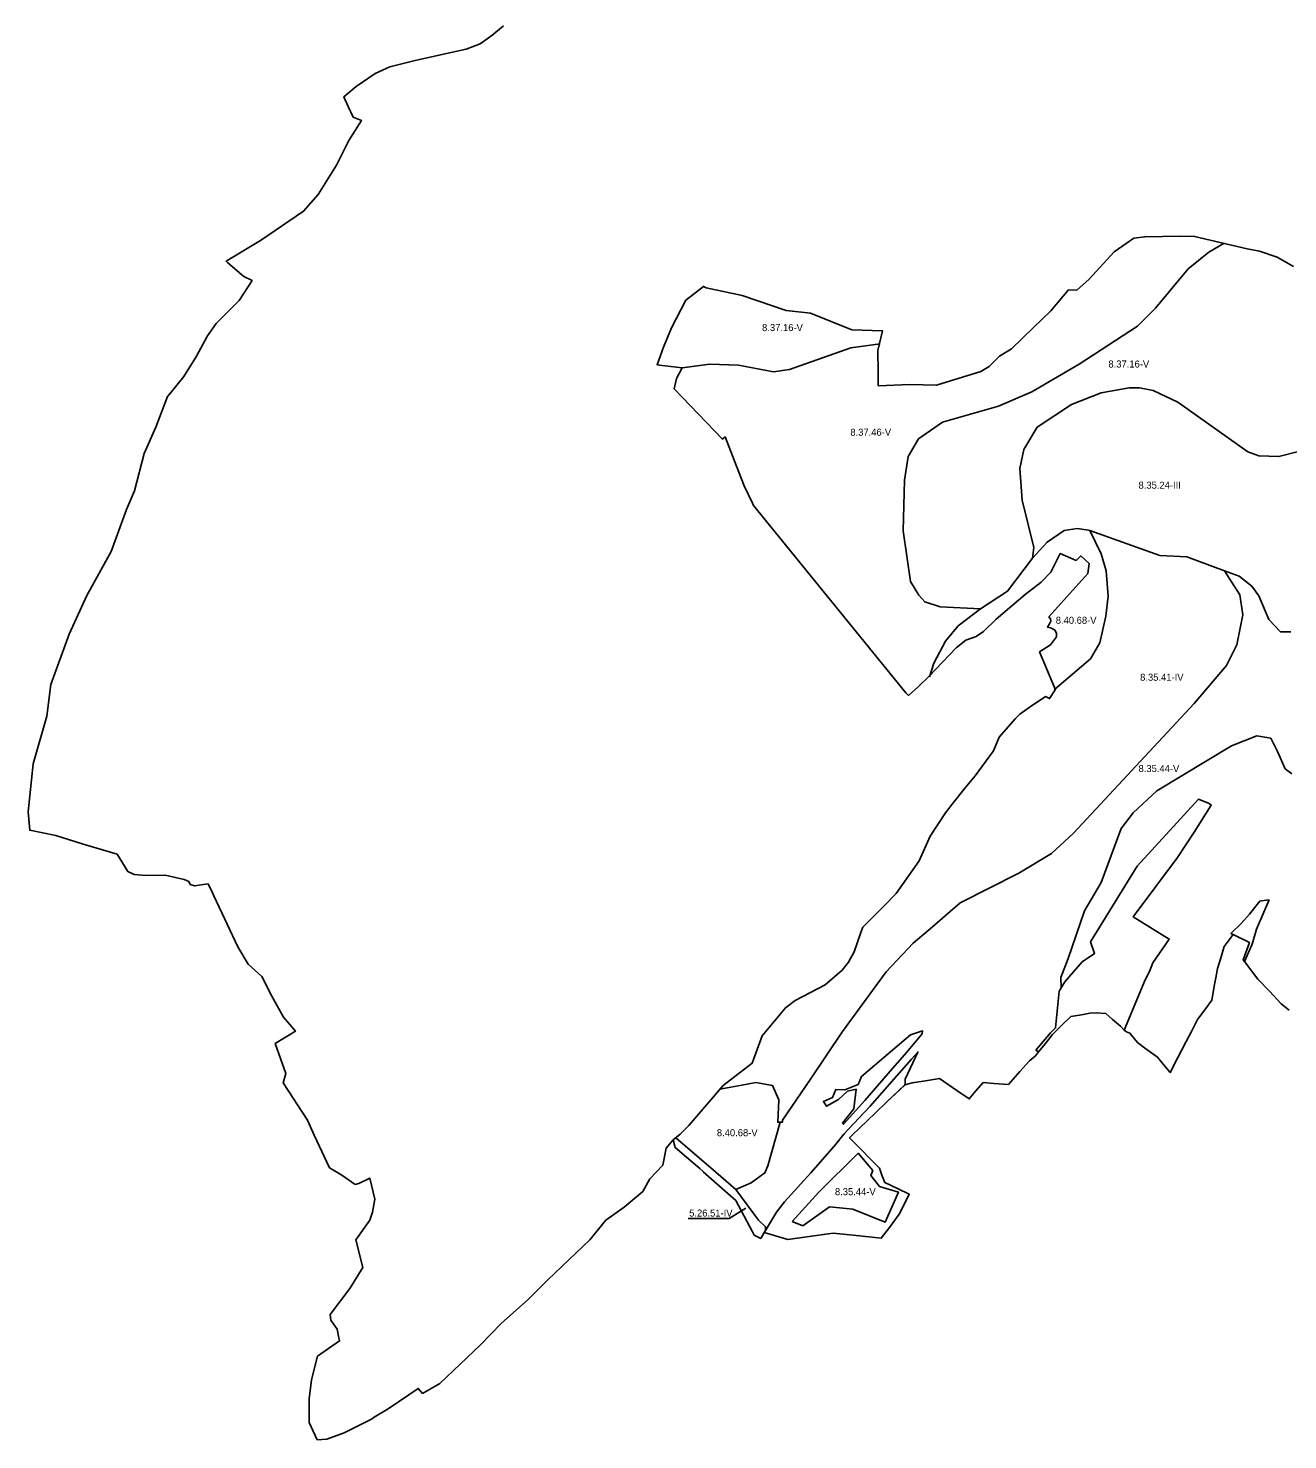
# Model space of a CAD drawing. Extents: x -547623 to -533936, y -1096714 to -1086523.
# Drawn here: x -547623 to -545832, y -1096380 to -1094374 of the extents above; entities that cross this region are included whole.
import ezdxf

# ---------------------------------------------------------------- set-up
doc = ezdxf.new("R2010")
doc.units = 0
doc.layers.add('Vrstva 27', color=7, linetype='Continuous')
doc.layers.add('Vrstva 28', color=7, linetype='Continuous')

msp = doc.modelspace()

# ---------------------------------------------------------------- linework, layer by layer
at = {"layer": 'Vrstva 27'}
msp.add_lwpolyline([(-546684.8, -1096065.7), (-546626.6, -1096065.7), (-546602.8, -1096050.9)], dxfattribs=at)
at = {"layer": 'Vrstva 28'}
for p, q in [((-545922.9, -1094679.3), (-545944.5, -1094692)), ((-545944.5, -1094692), (-545974, -1094715.5)), ((-545974, -1094715.5), (-546020.5, -1094771.5)), ((-546020.5, -1094771.5), (-546046, -1094797)), ((-546046, -1094797), (-546129, -1094851)), ((-546129, -1094851), (-546196.5, -1094890.5)), ((-546097.5, -1094892), (-546058, -1094885)), ((-546058, -1094885), (-546043, -1094885)), ((-546043, -1094885), (-546024, -1094888.5)), ((-546196.5, -1094890.5), (-546243.5, -1094911)), ((-546140, -1094908.5), (-546097.5, -1094892)), ((-546024, -1094888.5), (-545988.5, -1094905)), ((-545988.5, -1094905), (-545889, -1094976)), ((-546243.5, -1094911), (-546323.5, -1094933.5)), ((-546188.5, -1094941), (-546140, -1094908.5)), ((-546323.5, -1094933.5), (-546357.5, -1094957.5)), ((-546207.5, -1094972.5), (-546188.5, -1094941)), ((-546357.5, -1094957.5), (-546372, -1094982.5)), ((-546372, -1094982.5), (-546377.5, -1095016)), ((-546213.5, -1094999.5), (-546207.5, -1094972.5)), ((-545889, -1094976), (-545873.5, -1094981.5)), ((-545873.5, -1094981.5), (-545845, -1094982.5)), ((-545845, -1094982.5), (-545815, -1094975)), ((-546210, -1095044.5), (-546213.5, -1094999.5)), ((-546377.5, -1095016), (-546379.5, -1095088)), ((-546193.5, -1095112), (-546210, -1095044.5)), ((-546132, -1095085), (-546150.5, -1095087.5)), ((-546150.5, -1095087.5), (-546132, -1095085)), ((-546115.6, -1095087.4), (-546132, -1095085)), ((-546132, -1095085), (-546115.6, -1095087.4)), ((-546379.5, -1095088), (-546369, -1095160)), ((-546174.5, -1095104.5), (-546195.5, -1095127)), ((-546195.5, -1095127), (-546174.5, -1095104.5)), ((-546150.5, -1095087.5), (-546174.5, -1095104.5)), ((-546174.5, -1095104.5), (-546150.5, -1095087.5)), ((-546113.6, -1095087.7), (-546115.6, -1095087.4)), ((-546115.6, -1095087.4), (-546113.6, -1095087.7)), ((-546014.5, -1095123), (-546113.6, -1095087.7)), ((-546097.5, -1095121), (-546113.6, -1095087.7)), ((-546113.6, -1095087.7), (-546014.5, -1095123)), ((-546113.6, -1095087.7), (-546097.5, -1095121)), ((-546195.5, -1095127), (-546193.5, -1095112)), ((-546090.5, -1095145), (-546097.5, -1095121)), ((-546097.5, -1095121), (-546090.5, -1095145)), ((-545976, -1095125), (-546014.5, -1095123)), ((-546014.5, -1095123), (-545976, -1095125)), ((-545922.4, -1095144.8), (-545976, -1095125)), ((-545976, -1095125), (-545922.4, -1095144.8)), ((-546231, -1095174), (-546195.5, -1095127)), ((-546088, -1095181), (-546090.5, -1095145)), ((-546090.5, -1095145), (-546088, -1095181)), ((-545901.5, -1095152.5), (-545922.4, -1095144.8)), ((-545922.4, -1095144.8), (-545900.5, -1095179)), ((-545900.5, -1095179), (-545922.4, -1095144.8)), ((-545922.4, -1095144.8), (-545901.5, -1095152.5)), ((-546369, -1095160), (-546357, -1095179.5)), ((-545883.5, -1095167), (-545901.5, -1095152.5)), ((-545901.5, -1095152.5), (-545883.5, -1095167)), ((-546357, -1095179.5), (-546348.5, -1095189)), ((-546269.5, -1095199), (-546231, -1095174)), ((-546091, -1095209.5), (-546088, -1095181)), ((-546088, -1095181), (-546091, -1095209.5)), ((-545900.5, -1095179), (-545896.5, -1095207.5)), ((-545896.5, -1095207.5), (-545900.5, -1095179)), ((-545873.5, -1095180.5), (-545883.5, -1095167)), ((-545883.5, -1095167), (-545873.5, -1095180.5)), ((-545859.5, -1095214), (-545873.5, -1095180.5)), ((-545873.5, -1095180.5), (-545859.5, -1095214)), ((-546348.5, -1095189), (-546326.5, -1095196)), ((-546326.5, -1095196), (-546269.5, -1095199)), ((-546269.5, -1095199), (-546301, -1095223)), ((-546301, -1095223), (-546269.5, -1095199)), ((-546301, -1095223), (-546319, -1095245)), ((-546319, -1095245), (-546301, -1095223)), ((-546099.5, -1095247.5), (-546091, -1095209.5)), ((-546091, -1095209.5), (-546099.5, -1095247.5)), ((-545896.5, -1095207.5), (-545905, -1095250)), ((-545905, -1095250), (-545896.5, -1095207.5)), ((-545842.5, -1095231.5), (-545859.5, -1095214)), ((-545859.5, -1095214), (-545842.5, -1095231.5)), ((-546319, -1095245), (-546335.5, -1095276.5)), ((-546335.5, -1095276.5), (-546319, -1095245)), ((-545828, -1095231.5), (-545842.5, -1095231.5)), ((-545842.5, -1095231.5), (-545828, -1095231.5)), ((-546113, -1095270), (-546099.5, -1095247.5)), ((-546099.5, -1095247.5), (-546113, -1095270)), ((-545905, -1095250), (-545919.5, -1095279.5)), ((-545919.5, -1095279.5), (-545905, -1095250)), ((-546335.5, -1095276.5), (-546341.7, -1095295.9)), ((-546341.7, -1095295.9), (-546335.5, -1095276.5)), ((-546113, -1095270), (-546164.3, -1095313.6)), ((-546164.3, -1095313.6), (-546113, -1095270)), ((-545919.5, -1095279.5), (-545965.5, -1095333.5)), ((-545965.5, -1095333.5), (-545919.5, -1095279.5)), ((-545965.5, -1095333.5), (-546137, -1095518)), ((-546137, -1095518), (-545965.5, -1095333.5)), ((-545876.5, -1095379.5), (-545912.5, -1095394)), ((-545912.5, -1095394), (-545876.5, -1095379.5)), ((-545856.5, -1095383), (-545876.5, -1095379.5)), ((-545876.5, -1095379.5), (-545856.5, -1095383)), ((-545847, -1095402), (-545856.5, -1095383)), ((-545856.5, -1095383), (-545847, -1095402)), ((-545912.5, -1095394), (-546018.5, -1095458)), ((-546018.5, -1095458), (-545912.5, -1095394)), ((-545836, -1095426.5), (-545847, -1095402)), ((-545847, -1095402), (-545836, -1095426.5)), ((-545826.5, -1095433.5), (-545836, -1095426.5)), ((-545836, -1095426.5), (-545826.5, -1095433.5)), ((-546018.5, -1095458), (-546052, -1095489)), ((-546052, -1095489), (-546018.5, -1095458)), ((-546052, -1095489), (-546069.5, -1095511.5)), ((-546069.5, -1095511.5), (-546052, -1095489)), ((-546137, -1095518), (-546168.5, -1095547)), ((-546168.5, -1095547), (-546137, -1095518)), ((-546069.5, -1095511.5), (-546097.5, -1095588)), ((-546097.5, -1095588), (-546069.5, -1095511.5)), ((-546215, -1095575), (-546298, -1095617)), ((-546298, -1095617), (-546215, -1095575)), ((-546097.5, -1095588), (-546121.5, -1095628.5)), ((-546121.5, -1095628.5), (-546097.5, -1095588)), ((-546337.5, -1095650.9), (-546298, -1095617)), ((-546298, -1095617), (-546337.5, -1095650.9)), ((-546121.5, -1095628.5), (-546144.5, -1095696)), ((-546144.5, -1095696), (-546121.5, -1095628.5)), ((-546144.5, -1095696), (-546155, -1095723)), ((-546155, -1095723), (-546144.5, -1095696)), ((-546154.4, -1095737.8), (-546155, -1095723)), ((-546608.5, -1095876), (-546640.1, -1095882.1))]:
    msp.add_line(p, q, dxfattribs=at)
for points in [[(-546947.6, -1094370.1), (-546964.3, -1094383.9), (-546980.6, -1094395.6), (-547000.7, -1094403.5), (-547058.7, -1094416.3), (-547064.9, -1094417.6), (-547073, -1094419.6), (-547109.1, -1094428.7), (-547119.7, -1094433.3), (-547130.1, -1094437.8), (-547156.9, -1094456.7), (-547174.7, -1094471.2), (-547168.7, -1094484.7), (-547161.3, -1094500.2), (-547149.7, -1094504.6), (-547167.6, -1094533.1), (-547185, -1094568.5), (-547211, -1094609.9), (-547231.9, -1094633.8), (-547293, -1094675.2), (-547342, -1094705), (-547339.4, -1094707.2), (-547316.9, -1094726.4), (-547305.2, -1094732.3), (-547323.6, -1094760.5), (-547356.4, -1094793.3), (-547368.6, -1094810.8), (-547384.3, -1094839.8), (-547402.2, -1094868.6), (-547422.3, -1094893.2), (-547425.4, -1094897.3), (-547442.1, -1094940.7), (-547458.5, -1094978), (-547472.1, -1095031.1), (-547483.7, -1095057.9), (-547505.6, -1095117.6), (-547540.1, -1095180.3), (-547565.4, -1095235.1), (-547591.5, -1095306.5), (-547596.8, -1095351.7), (-547616.3, -1095419.4), (-547623.4, -1095487.8), (-547621.3, -1095513.9), (-547584, -1095521.3), (-547546.8, -1095532.9), (-547497, -1095547.9), (-547481.9, -1095572.4), (-547472.9, -1095576.5), (-547456.1, -1095578.2), (-547428.9, -1095577.9), (-547401.6, -1095583.7), (-547395, -1095586.6), (-547393.2, -1095590.8), (-547387.2, -1095592.7), (-547367.7, -1095589.8), (-547361, -1095603.9), (-547359.5, -1095607.1), (-547325.4, -1095679.6), (-547310.7, -1095704.4), (-547291.2, -1095721.7), (-547277.2, -1095749.8), (-547260.6, -1095779.7), (-547243.6, -1095799.5), (-547254.2, -1095805.9), (-547259.2, -1095809), (-547272.4, -1095817), (-547257.1, -1095859.5), (-547261.1, -1095872.9), (-547226.5, -1095925.9), (-547217, -1095947.4), (-547195.2, -1095993.6), (-547177.6, -1096004), (-547158.4, -1096017.2), (-547153.4, -1096015.9), (-547137.7, -1096008.4), (-547130.5, -1096038.5), (-547133.9, -1096056.9), (-547137.8, -1096067.9), (-547157.4, -1096096), (-547147.5, -1096135.5), (-547166.2, -1096165.4), (-547193.9, -1096202.3), (-547193.3, -1096210.3), (-547186.3, -1096219.7), (-547183.9, -1096223.3), (-547182, -1096232.9), (-547180.7, -1096239.7), (-547212.1, -1096261.6), (-547220.5, -1096294.9), (-547223, -1096314.4), (-547223.9, -1096321.2), (-547223.7, -1096355.7), (-547212.4, -1096380.3), (-547199, -1096379.3), (-547174.4, -1096370.6), (-547135.3, -1096350.8), (-547131.4, -1096348.4), (-547111.8, -1096336.5), (-547095.4, -1096325.4), (-547068.8, -1096307.4), (-547062.7, -1096314.4), (-547038.1, -1096300.4), (-546980.4, -1096245.5), (-546950.8, -1096215.2), (-546912, -1096180.6), (-546884.5, -1096153.1), (-546824.8, -1096095.9), (-546802.2, -1096067.9), (-546775.8, -1096049.8), (-546749.5, -1096027.5), (-546739.5, -1096009.2), (-546720.9, -1095989.9), (-546716.3, -1095965.8), (-546706.1, -1095954.1), (-546703.7, -1095964.6), (-546687.2, -1095978.8), (-546668.6, -1095994.9), (-546663.9, -1095999), (-546663.5, -1095999.3), (-546617.2, -1096040.2), (-546594.1, -1096083.9), (-546591.2, -1096089.3), (-546581.7, -1096094.2), (-546576.9, -1096085.7), (-546563.9, -1096089.4), (-546560.8, -1096090.3), (-546543.4, -1096095.6), (-546513.1, -1096091.5), (-546479, -1096086.8), (-546450.5, -1096089.6), (-546410.5, -1096093.9), (-546398.9, -1096078.6), (-546384.9, -1096059.8), (-546377.1, -1096044.1), (-546370.8, -1096031), (-546386.6, -1096023.7), (-546405.5, -1096014.8), (-546409.5, -1096004.3), (-546412.8, -1095994.4), (-546422.1, -1095985.2), (-546443.6, -1095963.1), (-546455.5, -1095951), (-546452.1, -1095947.7), (-546440.4, -1095936.5), (-546419.1, -1095916), (-546402.4, -1095900.1), (-546376.4, -1095875.5), (-546366.4, -1095873.1), (-546350.4, -1095870.5), (-546327.8, -1095866.9), (-546303, -1095883.9), (-546285.3, -1095895.7), (-546275.8, -1095884.4), (-546265.3, -1095872.3), (-546250.5, -1095873.9), (-546229.6, -1095875.4), (-546213.3, -1095856.8), (-546199.8, -1095841.5), (-546190.9, -1095834.4), (-546186.6, -1095828.9), (-546179.3, -1095819.6), (-546167.1, -1095804), (-546154.3, -1095791.5), (-546140.8, -1095778.8), (-546125.6, -1095776.1), (-546113.6, -1095774), (-546104.7, -1095773.2), (-546091.3, -1095774.5), (-546081.4, -1095783), (-546070.4, -1095792.5), (-546064.8, -1095797.9), (-546061.8, -1095800.2), (-546056.8, -1095802.4), (-546045.9, -1095815.7), (-546034.2, -1095824.4), (-546017.8, -1095836.2), (-546009.6, -1095846.5), (-545999.5, -1095858.4), (-545989, -1095838), (-545977, -1095814), (-545969.4, -1095799.7), (-545960.6, -1095782.7), (-545950.5, -1095769.1), (-545940.4, -1095755.3), (-545936.5, -1095733.3), (-545934.8, -1095723.6), (-545932.1, -1095710.3), (-545928.7, -1095698.3), (-545923, -1095679), (-545910.1, -1095661.9), (-545886.9, -1095673.6), (-545895.9, -1095698.2), (-545894.1, -1095700.6), (-545874.8, -1095725.4), (-545858.3, -1095742.7), (-545841.6, -1095760.7), (-545830.6, -1095769.5)], [(-546947.6, -1094370.1), (-546964.3, -1094383.9), (-546980.6, -1094395.6), (-547000.7, -1094403.5), (-547058.7, -1094416.3), (-547064.9, -1094417.6), (-547073, -1094419.6), (-547109.1, -1094428.7), (-547119.7, -1094433.3), (-547130.1, -1094437.8), (-547156.9, -1094456.7), (-547174.7, -1094471.2), (-547168.7, -1094484.7), (-547161.3, -1094500.2), (-547149.7, -1094504.6), (-547167.6, -1094533.1), (-547185, -1094568.5), (-547211, -1094609.9), (-547231.9, -1094633.8), (-547293, -1094675.2), (-547342, -1094705), (-547339.4, -1094707.2), (-547316.9, -1094726.4), (-547305.2, -1094732.3), (-547323.6, -1094760.5), (-547356.4, -1094793.3), (-547368.6, -1094810.8), (-547384.3, -1094839.8), (-547402.2, -1094868.6), (-547422.3, -1094893.2), (-547425.4, -1094897.3), (-547442.1, -1094940.7), (-547458.5, -1094978), (-547472.1, -1095031.1), (-547483.7, -1095057.9), (-547505.6, -1095117.6), (-547540.1, -1095180.3), (-547565.4, -1095235.1), (-547591.5, -1095306.5), (-547596.8, -1095351.7), (-547616.3, -1095419.4), (-547623.4, -1095487.8), (-547621.3, -1095513.9), (-547584, -1095521.3), (-547546.8, -1095532.9), (-547497, -1095547.9), (-547481.9, -1095572.4), (-547472.9, -1095576.5), (-547456.1, -1095578.2), (-547428.9, -1095577.9), (-547401.6, -1095583.7), (-547395, -1095586.6), (-547393.2, -1095590.8), (-547387.2, -1095592.7), (-547367.7, -1095589.8), (-547361, -1095603.9), (-547359.5, -1095607.1), (-547325.4, -1095679.6), (-547310.7, -1095704.4), (-547291.2, -1095721.7), (-547277.2, -1095749.8), (-547260.6, -1095779.7), (-547243.6, -1095799.5), (-547254.2, -1095805.9), (-547259.2, -1095809), (-547272.4, -1095817), (-547257.1, -1095859.5), (-547261.1, -1095872.9), (-547226.5, -1095925.9), (-547217, -1095947.4), (-547195.2, -1095993.6), (-547177.6, -1096004), (-547158.4, -1096017.2), (-547153.4, -1096015.9), (-547137.7, -1096008.4), (-547130.5, -1096038.5), (-547133.9, -1096056.9), (-547137.8, -1096067.9), (-547157.4, -1096096), (-547147.5, -1096135.5), (-547166.2, -1096165.4), (-547193.9, -1096202.3), (-547193.3, -1096210.3), (-547186.3, -1096219.7), (-547183.9, -1096223.3), (-547182, -1096232.9), (-547180.7, -1096239.7), (-547212.1, -1096261.6), (-547220.5, -1096294.9), (-547223, -1096314.4), (-547223.9, -1096321.2), (-547223.7, -1096355.7), (-547212.4, -1096380.3), (-547199, -1096379.3), (-547174.4, -1096370.6), (-547135.3, -1096350.8), (-547131.4, -1096348.4), (-547111.8, -1096336.5), (-547095.4, -1096325.4), (-547068.8, -1096307.4), (-547062.7, -1096314.4), (-547038.1, -1096300.4), (-546980.4, -1096245.5), (-546950.8, -1096215.2), (-546912, -1096180.6), (-546884.5, -1096153.1), (-546824.8, -1096095.9), (-546802.2, -1096067.9), (-546775.8, -1096049.8), (-546749.5, -1096027.5), (-546739.5, -1096009.2), (-546720.9, -1095989.9), (-546716.3, -1095965.8), (-546706.1, -1095954.1), (-546696.3, -1095946.1), (-546683.9, -1095933.6), (-546635.1, -1095876.9), (-546594.2, -1095845), (-546579.7, -1095806), (-546546.5, -1095766.5), (-546533, -1095755.9), (-546490, -1095733.8), (-546466.1, -1095712.6), (-546457, -1095701.5), (-546449.1, -1095686.7), (-546439.6, -1095659.2), (-546436.5, -1095651.7), (-546406.4, -1095621.2), (-546389.3, -1095603.6), (-546356.5, -1095557.2), (-546340.7, -1095522.1), (-546319.2, -1095489), (-546309.4, -1095476.6), (-546291, -1095453.4), (-546276.8, -1095436.6), (-546250.9, -1095400.9), (-546242.8, -1095381.7), (-546220, -1095355.5), (-546213.5, -1095348.7), (-546200.3, -1095339.1), (-546176.9, -1095323.8), (-546173.8, -1095325), (-546171.1, -1095326.6), (-546162.9, -1095314), (-546164.2, -1095310.7), (-546185.2, -1095260), (-546169.7, -1095250.3), (-546161.3, -1095238.8), (-546161.1, -1095233.5), (-546163.5, -1095229.2), (-546168.4, -1095226.6), (-546174.1, -1095225.1), (-546171.3, -1095220.6), (-546169.5, -1095216.4), (-546169.7, -1095213.2), (-546172.1, -1095210.2), (-546116.5, -1095148.7), (-546114.7, -1095134.7), (-546126.4, -1095123.8), (-546133.3, -1095130.1), (-546155.9, -1095120.5), (-546169.4, -1095147.1), (-546183.1, -1095161.1), (-546205.7, -1095178.8), (-546247.2, -1095213.8), (-546265.2, -1095231.3), (-546275.5, -1095238.4), (-546290.2, -1095243.7), (-546303.8, -1095254.4), (-546342.1, -1095294.9), (-546357.9, -1095309.9), (-546371.9, -1095322.2), (-546375.6, -1095318.3), (-546591.9, -1095052.2), (-546593.6, -1095049), (-546605.2, -1095024.1), (-546619.6, -1094987.9), (-546632.4, -1094954.6), (-546636.1, -1094957.7), (-546705.1, -1094886.1), (-546701.7, -1094871.4), (-546693.7, -1094856.6), (-546725.7, -1094852.5), (-546729.3, -1094852), (-546720.3, -1094827.1), (-546708.8, -1094799.4), (-546688.4, -1094760.3), (-546663.4, -1094740.6), (-546659.6, -1094742.7), (-546608.2, -1094753.6), (-546545.8, -1094774.7), (-546510.9, -1094778.7), (-546452.4, -1094802.3), (-546408.6, -1094803.9), (-546415.3, -1094831.9), (-546415, -1094862.3), (-546414.7, -1094882.1), (-546370, -1094880.2), (-546332, -1094881.2), (-546268.8, -1094861.7), (-546256.9, -1094854.3), (-546242.1, -1094839.8), (-546225.3, -1094829.3), (-546194.3, -1094799.4), (-546169.5, -1094775.5), (-546144.1, -1094745.5), (-546132.4, -1094746.2), (-546115, -1094730.6), (-546079, -1094691.6), (-546051.5, -1094672), (-546035.4, -1094670.2), (-545984.8, -1094669.3), (-545965, -1094669.6), (-545889.9, -1094687.2), (-545872.5, -1094690.6), (-545847.3, -1094699.1), (-545824.3, -1094712.4)], [(-546654.1, -1094851.4), (-546613.6, -1094852.6), (-546563.6, -1094861.9), (-546541.1, -1094858.9), (-546453.6, -1094827.9), (-546411.8, -1094822.2)], [(-546693.7, -1094856.6), (-546654.1, -1094851.4)], [(-545889, -1094976), (-545988.5, -1094905), (-546024, -1094888.5), (-546043, -1094885), (-546058, -1094885), (-546097.5, -1094892), (-546140, -1094908.5), (-546188.5, -1094941), (-546207.5, -1094972.5), (-546213.5, -1094999.5), (-546210, -1095044.5), (-546193.5, -1095112), (-546195.5, -1095127), (-546174.5, -1095104.5), (-546150.5, -1095087.5), (-546132, -1095085), (-546115.6, -1095087.4), (-546113.6, -1095087.7), (-546014.5, -1095123), (-545976, -1095125), (-545922.4, -1095144.8), (-545901.5, -1095152.5), (-545883.5, -1095167), (-545873.5, -1095180.5), (-545859.5, -1095214), (-545842.5, -1095231.5), (-545828, -1095231.5)], [(-545815, -1094975), (-545845, -1094982.5), (-545873.5, -1094981.5), (-545889, -1094976)], [(-546164.3, -1095313.6), (-546113, -1095270), (-546099.5, -1095247.5), (-546091, -1095209.5), (-546088, -1095181), (-546090.5, -1095145), (-546097.5, -1095121), (-546113.6, -1095087.7), (-546115.6, -1095087.4), (-546132, -1095085), (-546150.5, -1095087.5), (-546174.5, -1095104.5), (-546195.5, -1095127), (-546231, -1095174), (-546269.5, -1095199), (-546301, -1095223), (-546319, -1095245), (-546335.5, -1095276.5), (-546341.7, -1095295.9)], [(-545828, -1095231.5), (-545842.5, -1095231.5), (-545859.5, -1095214), (-545873.5, -1095180.5), (-545883.5, -1095167), (-545901.5, -1095152.5), (-545922.4, -1095144.8), (-545900.5, -1095179), (-545896.5, -1095207.5), (-545905, -1095250), (-545919.5, -1095279.5), (-545965.5, -1095333.5), (-546137, -1095518), (-546168.5, -1095547), (-546215, -1095575), (-546298, -1095617), (-546337.6, -1095651), (-546365, -1095674.5), (-546403.5, -1095715), (-546465.5, -1095800), (-546511, -1095867.5), (-546551, -1095926), (-546551, -1095929), (-546554, -1095929)], [(-546154.4, -1095737.7), (-546157.3, -1095742.5), (-546162.6, -1095794.8), (-546169.8, -1095801.7), (-546190.5, -1095826.4), (-546186.6, -1095828.9), (-546179.3, -1095819.6), (-546167.1, -1095804), (-546154.3, -1095791.5), (-546140.8, -1095778.8), (-546125.6, -1095776.1), (-546113.6, -1095774), (-546104.7, -1095773.2), (-546091.3, -1095774.5), (-546081.4, -1095783), (-546070.4, -1095792.5), (-546064.8, -1095797.9), (-546035, -1095726.3), (-546029, -1095714.5), (-546024.4, -1095702.2), (-546000.8, -1095668.6), (-546052, -1095636.9), (-545989.4, -1095552.5), (-545965.6, -1095516.6), (-545941.1, -1095478.1), (-545944, -1095475.6), (-545959.4, -1095469.4), (-546046.7, -1095564.7), (-546112.8, -1095672.3), (-546107.2, -1095688.8), (-546124.6, -1095701.1), (-546149.6, -1095729.4), (-546154.4, -1095737.7)], [(-545859, -1095612.6), (-545869.5, -1095614.2), (-545872.1, -1095614.6), (-545886.6, -1095632.9), (-545898.8, -1095646.2), (-545913.3, -1095660.5), (-545910.1, -1095661.9), (-545886.9, -1095673.6), (-545895.9, -1095698.2), (-545894.1, -1095700.6), (-545883.1, -1095675.9), (-545877, -1095654.4), (-545859, -1095612.6)], [(-546374.7, -1095829.6), (-546352.2, -1095803), (-546351.6, -1095799.1), (-546368.7, -1095804.8), (-546438.7, -1095863.7), (-546443.5, -1095875.2), (-546462.2, -1095882.8), (-546475, -1095882.2), (-546479.6, -1095893.8), (-546492.6, -1095899.6), (-546488.4, -1095906.2), (-546471.4, -1095896.5), (-546458.6, -1095884.9), (-546446.2, -1095882.1), (-546449.5, -1095909.9), (-546465.6, -1095930.2), (-546464.3, -1095931.8), (-546434, -1095897.9), (-546400.7, -1095859.6), (-546374.7, -1095829.6)], [(-546575, -1096082.6), (-546576.9, -1096085.7), (-546563.9, -1096089.4), (-546560.8, -1096090.3), (-546543.4, -1096095.6), (-546513.1, -1096091.5), (-546479, -1096086.8), (-546450.5, -1096089.6), (-546410.5, -1096093.9), (-546398.9, -1096078.6), (-546384.9, -1096059.8), (-546377.1, -1096044.1), (-546370.8, -1096031), (-546386.6, -1096023.7), (-546405.5, -1096014.8), (-546409.5, -1096004.3), (-546412.8, -1095994.4), (-546422.1, -1095985.2), (-546443.6, -1095963.1), (-546455.5, -1095951), (-546452.1, -1095947.7), (-546440.4, -1095936.5), (-546419.1, -1095916), (-546402.4, -1095900.1), (-546377.4, -1095876.4), (-546376.4, -1095875.5), (-546376.6, -1095867.6), (-546358.2, -1095829.1), (-546367.5, -1095839.4), (-546392.3, -1095867.2), (-546426.3, -1095905.9), (-546457.6, -1095939.4), (-546463.5, -1095945.8), (-546476.9, -1095962.3), (-546510.8, -1096000.6), (-546548, -1096042.2), (-546559.4, -1096056.7), (-546575, -1096082.6)], [(-546702.7, -1095951.3), (-546645.7, -1096000), (-546617, -1096024.5), (-546595.5, -1096015), (-546576, -1096001), (-546575.6, -1096000), (-546571.5, -1095991), (-546554, -1095929), (-546557.5, -1095929), (-546556, -1095897), (-546565, -1095876.5), (-546589, -1095872.5), (-546608.5, -1095876)], [(-546536.9, -1096069.8), (-546499.2, -1096028.5), (-546443.2, -1095972.9), (-546422.5, -1095997.5), (-546425.4, -1096004.7), (-546412.9, -1096020.1), (-546386.1, -1096028.1), (-546405, -1096071.2), (-546450.7, -1096052.6), (-546484, -1096049), (-546522, -1096076), (-546536.9, -1096069.8)], [(-546617, -1096024.5), (-546585, -1096068), (-546575, -1096077.5), (-546575, -1096083)]]:
    msp.add_lwpolyline(points, dxfattribs=at)

# ---------------------------------------------------------------- texts
at = {"layer": 'Vrstva 27'}
for s, p in [('8.37.16-V', (-546579.9, -1094804.2)), ('8.37.16-V', (-546087.4, -1094856)), ('8.37.46-V', (-546454.4, -1094953)), ('8.35.24-III', (-546044.6, -1095028.3)), ('8.40.68-V', (-546162.3, -1095220.3)), ('8.35.41-IV', (-546042.3, -1095301.3)), ('8.35.44-V', (-546044.6, -1095431.1)), ('8.40.68-V', (-546644.2, -1095948.8)), ('8.35.44-V', (-546476.3, -1096032.6)), ('5.26.51-IV', (-546683.6, -1096063))]:
    msp.add_text(s, height=10, dxfattribs=at).set_placement(p)

doc.saveas('drawing.dxf')
